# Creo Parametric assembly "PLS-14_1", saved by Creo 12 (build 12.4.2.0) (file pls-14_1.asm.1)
Units: Custom; MM, KILOGRAM, SECS

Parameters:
  PTC_WM_ITERATION = "0"
  PTC_WM_VERSION = "-.0"
  PTC_WM_LIFECYCLE_STATE = "In Work"
  PTC_WM_LIFECYCLE = "MO_CADDocument"
  PTC_WM_CREATED_BY = "Maximilian Roepper (Z0017RMS: MO)"
  PTC_WM_CREATED_ON = "18-Sep-26 11:36:42 AM"
  PTC_WM_MODIFIED_BY = "Maximilian Roepper (Z0017RMS: MO)"
  PTC_WM_MODIFIED_ON = "18-Sep-26 11:36:46 AM"
  PDMLINKNUMBER = "PDM000071455214"
  PTC_WM_NUMBER = "PDM000071455214"

Other parameters: WEIGHT, WEIGHT_FACTOR, WEIGHT_ADD, MC_ERRORS, SUPPLIER

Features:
  1. coordinate system
  2. imported feature
  3. component "FRAME_1_2"
  4. component "PIN01_1"
  5. component "PIN002_1"
  6. component "PIN003_1"
  7. component "PIN004_1"
  8. component "PIN005_1"
  9. component "PIN006_1"
  10. component "PIN007_1"
  11. component "PIN008_1"
  12. component "PIN009_1"
  13. component "PIN010_1"
  14. component "PIN011_1"
  15. component "PIN012_1"
  16. component "PIN013_1"
  17. component "PIN014_1"

Other named items: DRW_VIEW_ORG, ROUGH-GROB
